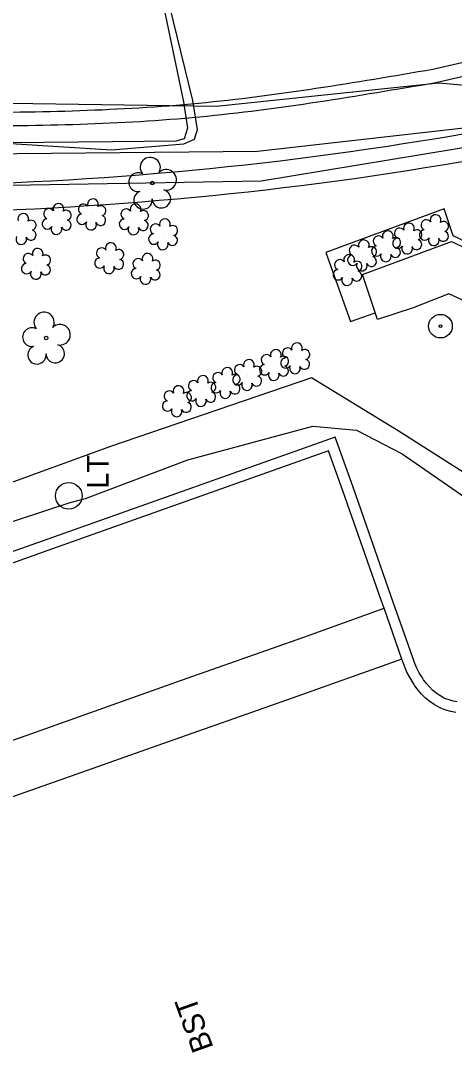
# Model space of a CAD drawing. Extents: x 1614611 to 1617571, y 898867 to 905462.
# Drawn here: x 1616028.5 to 1616108.4, y 903837.4 to 904028 of the extents above; entities that cross this region are included whole.
import ezdxf

# ---------------------------------------------------------------- set-up
doc = ezdxf.new("R2010")
doc.units = 0
for name, color, linetype in [('Exist Boundary Watershed Residential C 05', 7, 'Continuous'), ('Exist Building', 7, 'Continuous'), ('Exist Other Culture Fence Line', 7, 'Continuous'), ('Exist Other Culture Located Object CELL', 7, 'Continuous'), ('Exist Roads Change in Surface', 7, 'Continuous'), ('Exist Roads EOP Other Text', 7, 'Continuous'), ('Exist Utilities Other Pole CELL', 7, 'Continuous'), ('Exist Utilities Other Pole Text', 7, 'Continuous'), ('Exist Utilities Telephone UG Cable SUE LOS B', 7, 'Continuous'), ('Exist Utilities Telephone UG FO SUE LOS B', 7, 'Continuous'), ('Exist Vegetation Shrub CELL', 7, 'Continuous'), ('Exist Vegetation Tree CELL', 7, 'Continuous'), ('Prop Drainage Structure Catch Basin Grate 840 03E Label', 7, 'Continuous'), ('Prop Earthen Structure Cut Ditch Special Back of Curb Detail CELL', 7, 'Continuous'), ('Prop Earthen Structure Head Ditch Label', 7, 'Continuous'), ('Scratch_Level_1', 7, 'Continuous'), ('Scratch_Level_9', 7, 'Continuous')]:
    doc.layers.add(name, color=color, linetype=linetype)

msp = doc.modelspace()

# ---------------------------------------------------------------- linework, layer by layer
at = {"layer": 'Exist Boundary Watershed Residential C 05'}
msp.add_line((1616104.95, 904016.64), (1616134.69, 904023.46), dxfattribs=at)
msp.add_lwpolyline([(1616108.91, 903902.42), (1616108.15, 903902.57), (1616107.4, 903902.78), (1616106.65, 903903.06), (1616106.39, 903903.18), (1616105.7, 903903.58), (1616105.02, 903904.06), (1616104.37, 903904.59), (1616103.77, 903905.17), (1616103.23, 903905.8), (1616102.72, 903906.48), (1616102.49, 903906.83), (1616101.92, 903907.78), (1616101.42, 903908.75), (1616100.98, 903909.78), (1616100.95, 903909.87), (1616096.76, 903921.86), (1616089.71, 903941.99), (1616086.41, 903951.21), (1616034.54, 903932.81), (1616016.42, 903926.38)], dxfattribs=at)
msp.add_spline([(1615931.47, 904013.3), (1615973.24, 904009.77), (1616017.42, 904008.63), (1616061.47, 904010.33), (1616104.95, 904016.64)], degree=3, dxfattribs=at)
at = {"layer": 'Exist Building'}
msp.add_lwpolyline([(1616138.53, 903953.31), (1616140.01, 903948.86), (1616152.79, 903953.28), (1616144.93, 903975.27), (1616139.72, 903973.43), (1616108.17, 903988.36), (1616106.52, 903993.33), (1616084.73, 903985.3), (1616089.24, 903972.57), (1616093.8, 903974.18)], dxfattribs=at)
msp.add_lwpolyline([(1616132.87, 903965.89), (1616107.33, 903977.68), (1616100.81, 903975.08), (1616094.22, 903972.93), (1616091.47, 903981.25), (1616107.86, 903987.3), (1616139.71, 903972.3), (1616145.59, 903955.68), (1616137.43, 903952.94)], close=True, dxfattribs=at)
at = {"layer": 'Exist Other Culture Fence Line'}
msp.add_lwpolyline([(1616211.35, 903767.58), (1616195.22, 903813.36), (1616186.56, 903825.42), (1616168.75, 903875.81), (1616153.63, 903916.5), (1616129.58, 903932.3), (1616098.05, 903952.43), (1616082.04, 903962.19), (1616045.01, 903949.52), (1616000.86, 903933.41), (1615934.86, 903910.4), (1615905.89, 903899.71)], dxfattribs=at)
at = {"layer": 'Exist Other Culture Located Object CELL'}
for radius in [2.18, 0.24]:
    msp.add_circle((1616105.81, 903971.71), radius, dxfattribs=at)
at = {"layer": 'Exist Roads Change in Surface'}
for points in [[(1615917.61, 903856.74), (1615934.11, 903862.61), (1615960.99, 903872.11), (1616029.5, 903896.23), (1616058.14, 903906.43), (1616080.48, 903914.29), (1616095.43, 903919.73)], [(1616098.71, 903910.33), (1616077.62, 903902.83), (1616054.59, 903894.66), (1616034.64, 903887.62), (1615960.72, 903861.55), (1615920.92, 903847.5)]]:
    msp.add_lwpolyline(points, dxfattribs=at)
at = {"layer": 'Exist Utilities Other Pole CELL'}
msp.add_circle((1616037.35, 903940.42), 2.46, dxfattribs=at)
at = {"layer": 'Exist Utilities Telephone UG Cable SUE LOS B'}
for points in [[(1616026.69, 904005.38), (1616045.24, 904004.22), (1616058.54, 904005.35), (1616060.53, 904006.18), (1616061.09, 904008), (1616060.18, 904013.3), (1616051.64, 904048.27), (1616045.75, 904072.82), (1616046, 904073.59), (1616047.09, 904074.14), (1616056.45, 904077.41), (1616076.37, 904085.68), (1616087.72, 904092.48), (1616099.17, 904102.4), (1616105.02, 904109.27), (1616107.22, 904121.45), (1616104.45, 904136.97), (1616098.59, 904154.18), (1616090.72, 904180.29), (1616083.94, 904202.85), (1616081.35, 904206.54)], [(1616081.51, 904206.41), (1616083.24, 904202.62), (1616089.99, 904180.03), (1616097.97, 904153.91), (1616103.76, 904136.91), (1616106.57, 904121.53), (1616104.09, 904109.65), (1616098.94, 904102.77), (1616087.46, 904092.95), (1616076.12, 904086.3), (1616055.76, 904078.32), (1616046.06, 904074.48), (1616045.32, 904073.93), (1616045.03, 904072.97), (1616051.18, 904048.12), (1616058.49, 904013.1), (1616059.21, 904008.2), (1616058.59, 904006.25), (1616057.07, 904005.82), (1616045.43, 904005.69), (1616026.41, 904005.5)]]:
    msp.add_lwpolyline(points, dxfattribs=at)
at = {"layer": 'Exist Utilities Telephone UG FO SUE LOS B'}
for points in [[(1616249.11, 903962.1), (1616244.79, 903961.17), (1616238.35, 903961.16), (1616200.69, 903950.89), (1616195.93, 903950.49), (1616193.23, 903952.67), (1616190.15, 903959.25), (1616186.96, 903970.12), (1616182.94, 903976.59), (1616168.24, 903986.65), (1616161.85, 903994.6), (1616153.95, 904004.6), (1616148.06, 904010.09), (1616140.82, 904013.46), (1616124.88, 904014.78), (1616105.51, 904016.53), (1616064.53, 904012.24), (1616026.51, 904012.8), (1615984.81, 904011.98), (1615950.8, 904014.23), (1615922.36, 904016.58), (1615897.75, 904017.11), (1615884.16, 904015.33), (1615877.39, 904015.58)], [(1616231.95, 903831.99), (1616208.49, 903896.38), (1616196.66, 903929.39), (1616185.98, 903956.69), (1616178.38, 903970.82), (1616170.63, 903982.39), (1616159.03, 903993.51), (1616152.27, 904000.63), (1616146.16, 904003.93), (1616135.11, 904008.46), (1616113.93, 904008.67), (1616072.1, 904003.93), (1616027.82, 904003.5), (1615985.23, 904002.2), (1615950.55, 904003.04), (1615906.43, 904005.88), (1615898.01, 904002.34)]]:
    msp.add_lwpolyline(points, dxfattribs=at)
at = {"layer": 'Exist Vegetation Shrub CELL'}
for p, q in [((1616035.21, 903991.28), (1616035.21, 903991.28)), ((1616041.58, 903992.14), (1616041.58, 903992.14)), ((1616049.41, 903991.22), (1616049.41, 903991.22)), ((1616028.74, 903989.44), (1616028.74, 903989.44)), ((1616104.7, 903989.23), (1616104.7, 903989.23)), ((1616054.81, 903988.47), (1616054.81, 903988.47)), ((1616099.78, 903987.7), (1616099.78, 903987.7)), ((1616095.88, 903986.26), (1616095.88, 903986.26)), ((1616044.88, 903984.06), (1616044.88, 903984.06)), ((1616091.47, 903984.57), (1616091.47, 903984.57)), ((1616031.4, 903983.03), (1616031.4, 903983.03)), ((1616051.62, 903982.09), (1616051.62, 903982.09)), ((1616088.77, 903981.89), (1616088.77, 903981.89)), ((1616079.14, 903965.61), (1616079.14, 903965.61)), ((1616070.3, 903962.53), (1616070.3, 903962.53)), ((1616075.25, 903964.37), (1616075.25, 903964.37)), ((1616066.31, 903961.06), (1616066.31, 903961.06)), ((1616061.83, 903959.57), (1616061.83, 903959.57)), ((1616057.35, 903957.68), (1616057.35, 903957.68))]:
    msp.add_line(p, q, dxfattribs=at)
for centre, radius, start, end in [((1616041.81, 903994.18), 0.99, 334.8391, 200.4717), ((1616033.72, 903992.41), 0.968, 35.8908, 245.4216), ((1616035.44, 903993.32), 0.99, 334.8391, 200.4717), ((1616036.88, 903992.15), 0.929, 284.4567, 126.0861), ((1616040.09, 903993.26), 0.968, 35.8908, 245.4216), ((1616043.25, 903993), 0.929, 284.4567, 126.0861), ((1616047.93, 903992.35), 0.968, 35.8908, 245.4216), ((1616049.64, 903993.26), 0.99, 334.8391, 200.4717), ((1616028.97, 903991.48), 0.99, 334.8391, 200.4717), ((1616030.41, 903990.31), 0.929, 284.4567, 126.0861), ((1616033.41, 903990.58), 0.955, 95.1099, 327.9534), ((1616036.84, 903990.35), 0.937, 204.9913, 73.4601), ((1616039.78, 903991.43), 0.955, 95.1099, 327.9534), ((1616043.21, 903991.21), 0.937, 204.9913, 73.4601), ((1616047.61, 903990.52), 0.955, 95.1099, 327.9534), ((1616051.05, 903990.29), 0.937, 204.9913, 73.4601), ((1616051.09, 903992.09), 0.929, 284.4567, 126.0861), ((1616055.04, 903990.51), 0.99, 334.8391, 200.4717), ((1616103.22, 903990.36), 0.968, 35.8908, 245.4216), ((1616104.93, 903991.27), 0.99, 334.8391, 200.4717), ((1616030.38, 903988.51), 0.937, 204.9913, 73.4601), ((1616035.08, 903989.6), 0.984, 151.2797, 21.387), ((1616041.45, 903990.45), 0.984, 151.2797, 21.387), ((1616049.29, 903989.54), 0.984, 151.2797, 21.387), ((1616053.33, 903989.59), 0.968, 35.8908, 245.4216), ((1616056.48, 903989.34), 0.929, 284.4567, 126.0861), ((1616096.11, 903988.3), 0.99, 334.8391, 200.4717), ((1616098.3, 903988.82), 0.968, 35.8908, 245.4216), ((1616100.01, 903989.74), 0.99, 334.8391, 200.4717), ((1616101.46, 903988.56), 0.929, 284.4567, 126.0861), ((1616102.9, 903988.53), 0.955, 95.1099, 327.9534), ((1616106.37, 903990.1), 0.929, 284.4567, 126.0861), ((1616028.61, 903987.76), 0.984, 151.2797, 21.387), ((1616053.01, 903987.76), 0.955, 95.1099, 327.9534), ((1616056.45, 903987.54), 0.937, 204.9913, 73.4601), ((1616091.69, 903986.61), 0.99, 334.8391, 200.4717), ((1616094.4, 903987.39), 0.968, 35.8908, 245.4216), ((1616097.55, 903987.13), 0.929, 284.4567, 126.0861), ((1616097.98, 903986.99), 0.955, 95.1099, 327.9534), ((1616101.42, 903986.77), 0.937, 204.9913, 73.4601), ((1616104.57, 903987.55), 0.984, 151.2797, 21.387), ((1616106.34, 903988.3), 0.937, 204.9913, 73.4601), ((1616031.63, 903985.07), 0.99, 334.8391, 200.4717), ((1616043.4, 903985.19), 0.968, 35.8908, 245.4216), ((1616045.11, 903986.1), 0.99, 334.8391, 200.4717), ((1616046.55, 903984.93), 0.929, 284.4567, 126.0861), ((1616054.68, 903986.78), 0.984, 151.2797, 21.387), ((1616089.98, 903985.69), 0.968, 35.8908, 245.4216), ((1616093.14, 903985.44), 0.929, 284.4567, 126.0861), ((1616094.08, 903985.56), 0.955, 95.1099, 327.9534), ((1616097.52, 903985.33), 0.937, 204.9913, 73.4601), ((1616099.66, 903986.01), 0.984, 151.2797, 21.387), ((1616029.92, 903984.16), 0.968, 35.8908, 245.4216), ((1616033.08, 903983.9), 0.929, 284.4567, 126.0861), ((1616043.08, 903983.35), 0.955, 95.1099, 327.9534), ((1616046.52, 903983.13), 0.937, 204.9913, 73.4601), ((1616050.13, 903983.22), 0.968, 35.8908, 245.4216), ((1616051.85, 903984.13), 0.99, 334.8391, 200.4717), ((1616053.29, 903982.96), 0.929, 284.4567, 126.0861), ((1616087.28, 903983.01), 0.968, 35.8908, 245.4216), ((1616088.99, 903983.93), 0.99, 334.8391, 200.4717), ((1616089.66, 903983.86), 0.955, 95.1099, 327.9534), ((1616090.44, 903982.76), 0.929, 284.4567, 126.0861), ((1616093.1, 903983.64), 0.937, 204.9913, 73.4601), ((1616095.75, 903984.58), 0.984, 151.2797, 21.387), ((1616029.6, 903982.32), 0.955, 95.1099, 327.9534), ((1616031.28, 903981.35), 0.984, 151.2797, 21.387), ((1616033.04, 903982.1), 0.937, 204.9913, 73.4601), ((1616044.75, 903982.38), 0.984, 151.2797, 21.387), ((1616049.82, 903981.39), 0.955, 95.1099, 327.9534), ((1616053.25, 903981.16), 0.937, 204.9913, 73.4601), ((1616086.97, 903981.18), 0.955, 95.1099, 327.9534), ((1616090.4, 903980.96), 0.937, 204.9913, 73.4601), ((1616091.34, 903982.88), 0.984, 151.2797, 21.387), ((1616051.49, 903980.41), 0.984, 151.2797, 21.387), ((1616088.64, 903980.2), 0.984, 151.2797, 21.387), ((1616079.37, 903967.65), 0.99, 334.8391, 200.4717), ((1616073.77, 903965.5), 0.968, 35.8908, 245.4216), ((1616075.48, 903966.41), 0.99, 334.8391, 200.4717), ((1616077.66, 903966.74), 0.968, 35.8908, 245.4216), ((1616080.81, 903966.48), 0.929, 284.4567, 126.0861), ((1616068.82, 903963.66), 0.968, 35.8908, 245.4216), ((1616070.53, 903964.57), 0.99, 334.8391, 200.4717), ((1616073.45, 903963.66), 0.955, 95.1099, 327.9534), ((1616076.92, 903965.24), 0.929, 284.4567, 126.0861), ((1616077.34, 903964.91), 0.955, 95.1099, 327.9534), ((1616080.78, 903964.68), 0.937, 204.9913, 73.4601), ((1616062.06, 903961.61), 0.99, 334.8391, 200.4717), ((1616064.83, 903962.19), 0.968, 35.8908, 245.4216), ((1616066.54, 903963.1), 0.99, 334.8391, 200.4717), ((1616067.98, 903961.93), 0.929, 284.4567, 126.0861), ((1616068.5, 903961.82), 0.955, 95.1099, 327.9534), ((1616071.97, 903963.4), 0.929, 284.4567, 126.0861), ((1616075.12, 903962.69), 0.984, 151.2797, 21.387), ((1616076.89, 903963.44), 0.937, 204.9913, 73.4601), ((1616079.01, 903963.93), 0.984, 151.2797, 21.387), ((1616057.58, 903959.73), 0.99, 334.8391, 200.4717), ((1616060.35, 903960.7), 0.968, 35.8908, 245.4216), ((1616063.5, 903960.44), 0.929, 284.4567, 126.0861), ((1616064.51, 903960.36), 0.955, 95.1099, 327.9534), ((1616067.95, 903960.13), 0.937, 204.9913, 73.4601), ((1616070.17, 903960.85), 0.984, 151.2797, 21.387), ((1616071.94, 903961.6), 0.937, 204.9913, 73.4601), ((1616055.87, 903958.81), 0.968, 35.8908, 245.4216), ((1616059.02, 903958.55), 0.929, 284.4567, 126.0861), ((1616060.03, 903958.87), 0.955, 95.1099, 327.9534), ((1616063.47, 903958.64), 0.937, 204.9913, 73.4601), ((1616066.18, 903959.38), 0.984, 151.2797, 21.387), ((1616055.55, 903956.98), 0.955, 95.1099, 327.9534), ((1616058.99, 903956.76), 0.937, 204.9913, 73.4601), ((1616061.7, 903957.89), 0.984, 151.2797, 21.387), ((1616057.22, 903956), 0.984, 151.2797, 21.387)]:
    msp.add_arc(centre, radius, start, end, dxfattribs=at)
at = {"layer": 'Exist Vegetation Tree CELL'}
for p, q in [((1616052.75, 903998.1), (1616052.75, 903998.1)), ((1616033.19, 903969.54), (1616033.19, 903969.54))]:
    msp.add_line(p, q, dxfattribs=at)
for centre in [(1616052.75, 903998.1), (1616033.19, 903969.54)]:
    msp.add_circle(centre, 0.326, dxfattribs=at)
for centre, radius, start, end in [((1616052.36, 904000.98), 1.86, 330.1651, 219.7134), ((1616050.14, 903998.26), 1.73, 62.6636, 279.3457), ((1616055.3, 903998.69), 1.9, 257.1011, 134.1999), ((1616054.42, 903995.2), 1.7, 181.2822, 74.56), ((1616051.04, 903994.98), 1.69, 111.5671, 6.231), ((1616032.8, 903972.41), 1.86, 330.1651, 219.7134), ((1616030.58, 903969.69), 1.73, 62.6636, 279.3457), ((1616035.74, 903970.13), 1.9, 257.1011, 134.1999), ((1616034.86, 903966.64), 1.7, 181.2822, 74.56), ((1616031.49, 903966.42), 1.69, 111.5671, 6.231)]:
    msp.add_arc(centre, radius, start, end, dxfattribs=at)
at = {"layer": 'Prop Drainage Structure Catch Basin Grate 840 03E Label'}
for points in [[(1616175.37, 903932.73), (1616162.82, 903955.92), (1616154.05, 903981.84), (1616149.33, 903992.61), (1616140.12, 904002.5), (1616134.79, 904005.2), (1616125.79, 904006.53), (1616114.47, 904005.33), (1616072.77, 903998.44), (1616026.71, 903997.66), (1615985.03, 903997.01), (1615951.2, 903997.28), (1615903.82, 904001.29), (1615897.29, 903998.6), (1615887.7, 903992.46), (1615886.9, 903991.11)], [(1615923.93, 903899.6), (1615932.83, 903902.93), (1615946.29, 903906.03), (1615958.51, 903911.73), (1616004.36, 903928.24), (1616037.61, 903939.19), (1616040.41, 903939.94), (1616059.29, 903947.07), (1616082.31, 903953.27), (1616090.33, 903952.53), (1616098.78, 903948.15), (1616126.18, 903929.2), (1616146.2, 903914.72), (1616149.01, 903912.2)]]:
    msp.add_lwpolyline(points, dxfattribs=at)
at = {"layer": 'Prop Earthen Structure Cut Ditch Special Back of Curb Detail CELL'}
msp.add_arc((1615999.11, 904642.59), 650, 262.96391, 281.5172, dxfattribs=at)
at = {"layer": 'Prop Earthen Structure Head Ditch Label'}
msp.add_arc((1615999.11, 904642.59), 645, 262.96391, 281.5172, dxfattribs=at)
at = {"layer": 'Scratch_Level_1'}
msp.add_lwpolyline([(1616108.63, 903900.49), (1616107.7, 903900.66), (1616106.79, 903900.92), (1616105.91, 903901.25), (1616105.5, 903901.43), (1616104.64, 903901.93), (1616103.83, 903902.5), (1616103.07, 903903.13), (1616102.35, 903903.82), (1616101.7, 903904.57), (1616101.11, 903905.36), (1616100.83, 903905.79), (1616100.21, 903906.84), (1616099.65, 903907.92), (1616099.17, 903909.04), (1616099.11, 903909.19), (1616098.71, 903910.33), (1616095.43, 903919.73), (1616094.92, 903921.21), (1616087.86, 903941.34), (1616085.22, 903948.71), (1616035.19, 903930.97), (1616017.08, 903924.53)], dxfattribs=at)
at = {"layer": 'Scratch_Level_9'}
msp.add_line((1616104.38, 904019.1), (1616134.32, 904025.99), dxfattribs=at)
for points in [[(1616097.99, 904045.33), (1616058.52, 904034.87), (1616017.88, 904028.96), (1615976.43, 904026.45), (1615935.89, 904028.72)], [(1615931.62, 904015.71), (1615973.45, 904012.19), (1616017.45, 904011.12), (1616061.25, 904012.84), (1616104.38, 904019.1)]]:
    msp.add_spline(points, degree=3, dxfattribs=at)

# ---------------------------------------------------------------- texts
at = {"layer": 'Exist Roads EOP Other Text'}
msp.add_text('BST', height=4, rotation=109.6686, dxfattribs=at).set_placement((1616064.05, 903838.67))
at = {"layer": 'Exist Utilities Other Pole Text'}
msp.add_text('LT', height=4, rotation=90, dxfattribs=at).set_placement((1616044.68, 903941.72))

doc.saveas('drawing.dxf')
